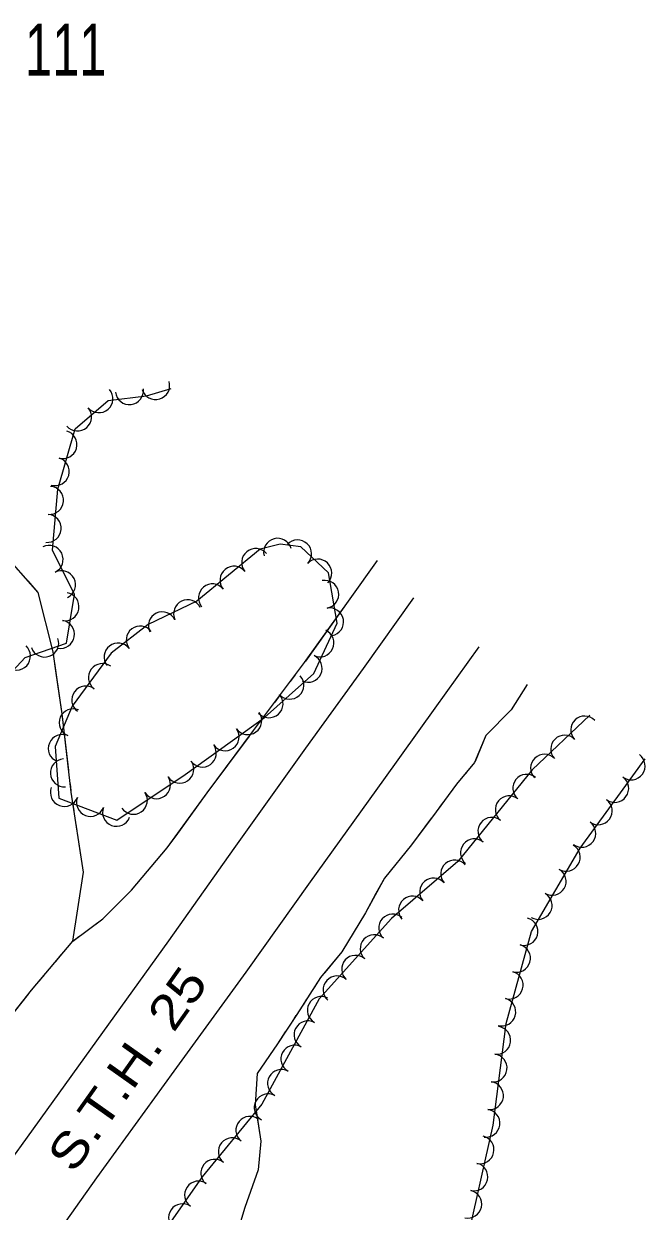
# Model space of a CAD drawing. Extents: x 297327 to 299792, y 46897 to 49095.
# Drawn here: x 298897.4 to 299076.7, y 48195.8 to 48538.9 of the extents above; entities that cross this region are included whole.
import ezdxf

# ---------------------------------------------------------------- set-up
doc = ezdxf.new("R2010")
doc.units = 0
doc.header["$LTSCALE"] = 2.4
for name, color, linetype, lineweight in [('11', 7, 'Continuous', 25), ('18', 7, 'Continuous', 13), ('19', 7, 'Continuous', 13), ('4', 7, 'Continuous', 13)]:
    doc.layers.add(name, color=color, linetype=linetype, lineweight=lineweight)

msp = doc.modelspace()

# ---------------------------------------------------------------- linework, layer by layer
at = {"layer": '11'}
for points in [[(298880.386, 48192.263), (298896.726, 48214.837), (298916.698, 48242.677), (298939.22, 48273.989), (298958.14, 48300.616), (298978.782, 48329.563), (298995.404, 48352.579), (299009.962, 48373.031)], [(298901.899, 48182.138), (298918.424, 48205.473), (298940.804, 48236.283), (298961.583, 48264.893), (298980.15, 48290.974), (299001.259, 48320.43), (299016.144, 48341.153), (299028.794, 48358.922)]]:
    msp.add_lwpolyline(points, dxfattribs=at)
at = {"layer": '18'}
for points in [[(298849.244, 48321.907), (298857.535, 48329.28), (298866.122, 48330.268), (298878.495, 48333.027), (298889.123, 48346.539), (298897.753, 48355.771), (298909.657, 48359.901), (298911.987, 48373.993), (298905.69, 48386.836), (298907.189, 48404.412), (298912.175, 48421.888), (298921.692, 48430.031), (298932.836, 48431.368), (298939.927, 48433.501)], [(299060.702, 48339.161), (299044.082, 48323.308), (299022.648, 48296.835), (299003.5, 48280.438), (298982.651, 48257.231), (298966.034, 48226.736), (298948.867, 48205.749), (298933.44, 48183.723)], [(299011.795, 47691.222), (299015.435, 47723.842), (299016.736, 47764.31), (299018.061, 47800.007), (299024.133, 47827.15), (299025.206, 47872.392), (299023.037, 47903.737), (299028.711, 47931.468), (299036.04, 47985.928), (299030.647, 48015.786), (299032.488, 48066.369), (299030.517, 48107.23), (299025.207, 48141.127), (299024.814, 48185.103), (299032.807, 48220.691), (299036.611, 48250.046), (299043.903, 48276.662), (299057.908, 48300.748), (299070.384, 48317.762), (299076.733, 48326.492)]]:
    msp.add_lwpolyline(points, dxfattribs=at)
msp.add_lwpolyline([(298947.358, 48372.097), (298933.295, 48365.306), (298922.622, 48357.058), (298911.335, 48341.734), (298906.425, 48330.086), (298907.522, 48315.14), (298924.212, 48308.783), (298943.918, 48322.03), (298966.858, 48338.423), (298981.077, 48351.182), (298987.848, 48365.715), (298985.274, 48380.216), (298977.321, 48387.767), (298971.326, 48388.581), (298965.64, 48387.075)], close=True, dxfattribs=at)
for centre, radius, start, end in [((298935.431, 48434.366), 4.058, 196.74915, 16.73383), ((298919.053, 48430.568), 4.058, 220.55884, 40.54352), ((298927.851, 48432.909), 4.058, 186.84902, 6.83369), ((298912.888, 48425.293), 4.058, 220.55884, 40.54352), ((298908.662, 48417.317), 4.058, 254.08392, 74.0686), ((298906.436, 48409.514), 4.058, 254.08392, 74.0686), ((298904.783, 48401.19), 4.058, 265.13289, 85.11756), ((298904.093, 48393.105), 4.058, 265.13289, 85.11756), ((298970.622, 48386.211), 4.033, 14.84245, 194.82713), ((298976.395, 48385.735), 4.033, 316.49294, 136.47762), ((298904.665, 48384.103), 4.058, 296.12665, 116.11133), ((298964.293, 48383.242), 4.033, 39.33459, 219.31927), ((298982.244, 48380.182), 4.033, 316.49294, 136.47762), ((298908.237, 48376.817), 4.058, 296.12665, 116.11133), ((298958.054, 48378.131), 4.033, 39.33459, 219.31927), ((298951.815, 48373.019), 4.033, 39.33459, 219.31927), ((298984.225, 48374.046), 4.033, 280.07311, 100.05779), ((298909.251, 48370.464), 4.058, 260.6192, 80.60388), ((298944.644, 48368.442), 4.033, 25.78348, 205.76816), ((298937.381, 48364.935), 4.033, 25.78348, 205.76816), ((298985.635, 48366.105), 4.033, 280.07311, 100.05779), ((298907.927, 48362.459), 4.058, 260.6192, 80.60388), ((298930.988, 48360.855), 4.033, 37.70419, 217.68887), ((298982.854, 48359.994), 4.033, 245.02661, 65.01128), ((298895.254, 48356.208), 4.058, 226.93796, 46.92264), ((298903.412, 48359.982), 4.058, 199.14148, 19.12616), ((298924.606, 48355.923), 4.033, 37.70419, 217.68887), ((298979.448, 48352.683), 4.033, 245.02661, 65.01128), ((298920.058, 48350.018), 4.033, 53.6339, 233.61858), ((298974.165, 48347.816), 4.033, 221.90994, 41.89462), ((298915.275, 48343.524), 4.033, 53.6339, 233.61858), ((298968.162, 48342.429), 4.033, 221.90994, 41.89462), ((298911.615, 48336.963), 4.033, 67.1507, 247.13538), ((298962.035, 48337.571), 4.033, 215.55739, 35.54206), ((299059.251, 48334.881), 4.004, 43.65461, 223.63929), ((298955.473, 48332.882), 4.033, 215.55739, 35.54206), ((298908.482, 48329.531), 4.033, 67.1507, 247.13538), ((299053.457, 48329.354), 4.004, 43.65461, 223.63929), ((298948.911, 48328.193), 4.033, 215.55739, 35.54206), ((299047.663, 48323.827), 4.004, 43.65461, 223.63929), ((298909.1, 48322.483), 4.033, 94.20551, 274.19018), ((298942.392, 48323.548), 4.033, 213.91791, 33.90259), ((299072.665, 48324.478), 4.023, 233.98068, 53.96536), ((298935.698, 48319.048), 4.033, 213.91791, 33.90259), ((299042.528, 48318.059), 4.004, 51.01212, 230.9968), ((299067.934, 48317.982), 4.023, 233.75587, 53.74054), ((298909.075, 48316.807), 4.033, 159.15649, 339.14116), ((298916.612, 48313.937), 4.033, 159.15649, 339.14116), ((298929.005, 48314.548), 4.033, 213.91791, 33.90259), ((299037.49, 48311.835), 4.004, 51.01212, 230.9968), ((299063.178, 48311.495), 4.023, 233.75587, 53.74054), ((298924.149, 48311.066), 4.033, 159.15649, 339.14116), ((299032.451, 48305.612), 4.004, 51.01212, 230.9968), ((299058.421, 48305.008), 4.023, 233.75587, 53.74054), ((299027.412, 48299.389), 4.004, 51.01212, 230.9968), ((299053.924, 48298.084), 4.023, 239.83146, 59.81613), ((299021.714, 48293.276), 4.004, 40.58209, 220.56676), ((299049.88, 48291.13), 4.023, 239.83146, 59.81613), ((299015.632, 48288.068), 4.004, 40.58209, 220.56676), ((299009.55, 48282.86), 4.004, 40.58209, 220.56676), ((299045.837, 48284.176), 4.023, 239.83146, 59.81613), ((299003.831, 48277.671), 4.004, 48.07137, 228.05605), ((299041.72, 48276.662), 4.023, 254.68626, 74.67094), ((298998.48, 48271.715), 4.004, 48.07137, 228.05605), ((298993.129, 48265.758), 4.004, 48.07137, 228.05605), ((299039.595, 48268.904), 4.023, 254.68626, 74.67094), ((298987.778, 48259.802), 4.004, 48.07137, 228.05605), ((299037.469, 48261.145), 4.023, 254.68626, 74.67094), ((298983.214, 48253.885), 4.004, 61.4213, 241.40598), ((299035.343, 48253.387), 4.023, 254.68626, 74.67094), ((298979.383, 48246.854), 4.004, 61.4213, 241.40598), ((299033.86, 48245.203), 4.023, 262.62407, 82.60875), ((298975.552, 48239.823), 4.004, 61.4213, 241.40598), ((299032.827, 48237.225), 4.023, 262.62407, 82.60875), ((298971.72, 48232.791), 4.004, 61.4213, 241.40598), ((299031.793, 48229.248), 4.023, 262.62407, 82.60875), ((298967.889, 48225.76), 4.004, 61.4213, 241.40598), ((299030.759, 48221.27), 4.023, 262.62407, 82.60875), ((298962.606, 48219.235), 4.004, 50.72509, 230.70977), ((298957.536, 48213.037), 4.004, 50.72509, 230.70977), ((299029.058, 48213.607), 4.023, 257.34919, 77.33387), ((298952.466, 48206.839), 4.004, 50.72509, 230.70977), ((299027.295, 48205.758), 4.023, 257.34919, 77.33387), ((298947.782, 48200.546), 4.004, 55.00028, 234.98496), ((299025.533, 48197.91), 4.023, 257.34919, 77.33387), ((298943.188, 48193.988), 4.004, 55.00028, 234.98496)]:
    msp.add_arc(centre, radius, start, end, dxfattribs=at)
at = {"layer": '19'}
for p, q in [((298974.318, 48348.839), (298975.796, 48350.809)), ((298969.882, 48342.93), (298971.36, 48344.9)), ((298965.446, 48337.02), (298966.925, 48338.99)), ((299025.329, 48322.855), (299024.119, 48321.422)), ((298911.04, 48317.318), (298910.814, 48319.26)), ((299021.742, 48318.52), (299020.629, 48317.01)), ((298911.909, 48311.517), (298911.615, 48313.45)), ((299018.402, 48313.99), (299017.288, 48312.48)), ((298912.792, 48305.718), (298912.498, 48307.651)), ((298906.588, 48267.988), (298908.173, 48269.874)), ((298901.833, 48262.328), (298903.418, 48264.215)), ((298982.033, 48261.801), (298981.016, 48260.226)), ((298978.982, 48257.074), (298977.965, 48255.499)), ((298975.928, 48252.349), (298974.902, 48250.779))]:
    msp.add_line(p, q, dxfattribs=at)
for points in [[(298911.507, 48273.843), (298914.609, 48293.775), (298911.084, 48316.942), (298908.451, 48339.55), (298905.863, 48357.417), (298901.52, 48374.62), (298894.442, 48382.699), (298887.513, 48390.656), (298883.466, 48400.762), (298880.607, 48405.88), (298872.229, 48414.032), (298865.894, 48424.534), (298860.761, 48434.598), (298857.367, 48442.376), (298852.093, 48455.572), (298847.442, 48465.754), (298842.16, 48475.328), (298839.187, 48482.326), (298837.213, 48487.053), (298836.315, 48488.339)], [(298878.383, 48229.255), (298884.484, 48239.773), (298890.633, 48248.377), (298899.59, 48259.658), (298911.507, 48273.843), (298920.17, 48280.279), (298928.495, 48288.556), (298938.783, 48300.785), (298950.348, 48316.747), (298963.7, 48334.694), (298978.43, 48354.318), (298991.544, 48372.761), (298999.485, 48383.835)], [(298978.742, 48354.757), (298991.544, 48372.761), (298999.485, 48383.835)], [(298906.755, 48351.257), (298905.863, 48357.417), (298901.52, 48374.62), (298898.632, 48377.916)], [(298910.362, 48323.143), (298908.451, 48339.55), (298906.755, 48351.257)], [(299042.661, 48348.046), (299038.015, 48340.659), (299030.735, 48333.262), (299027.5, 48325.424), (299022.259, 48319.221), (299015.304, 48309.788), (299009.244, 48301.67), (299001.46, 48292.094), (298996.003, 48282.076), (298989.165, 48270.782), (298983.026, 48263.34), (298976.155, 48252.695), (298970.579, 48244.17), (298964.734, 48235.622), (298964.122, 48226.618), (298965.8, 48216.127), (298965.039, 48207.854), (298961.166, 48196.914), (298957.122, 48183.527)], [(299042.661, 48348.046), (299038.015, 48340.659), (299030.735, 48333.262), (299027.648, 48325.783)], [(298941.33, 48304.301), (298950.348, 48316.747), (298962.496, 48333.075)], [(299015.06, 48309.461), (299009.244, 48301.67), (299001.46, 48292.094), (298999.001, 48287.581)], [(298917.232, 48278.096), (298920.17, 48280.279), (298928.495, 48288.556), (298938.783, 48300.785), (298941.33, 48304.301)], [(298911.507, 48273.843), (298914.609, 48293.775), (298913.38, 48301.851)], [(298999.001, 48287.581), (298996.003, 48282.076), (298989.165, 48270.782), (298984.248, 48264.822)], [(298911.342, 48273.647), (298911.507, 48273.843), (298913.278, 48275.159)], [(298878.383, 48229.255), (298884.484, 48239.773), (298890.633, 48248.377), (298898.695, 48258.53)], [(298972.848, 48247.64), (298970.579, 48244.17), (298964.734, 48235.622), (298964.122, 48226.618), (298964.703, 48222.983)], [(298964.703, 48222.983), (298965.8, 48216.127), (298965.039, 48207.854), (298961.166, 48196.914), (298961.063, 48196.572)]]:
    msp.add_lwpolyline(points, dxfattribs=at)

# ---------------------------------------------------------------- texts
at = {"layer": '11', "width": 1.2}
msp.add_text('S.T.H. 25', height=10, rotation=54.695, dxfattribs=at).set_placement((298911.751, 48206.432))
at = {"layer": '4', "width": 0.7}
msp.add_text('111', height=15, dxfattribs=at).set_placement((298897.757, 48523.861))

doc.saveas('drawing.dxf')
